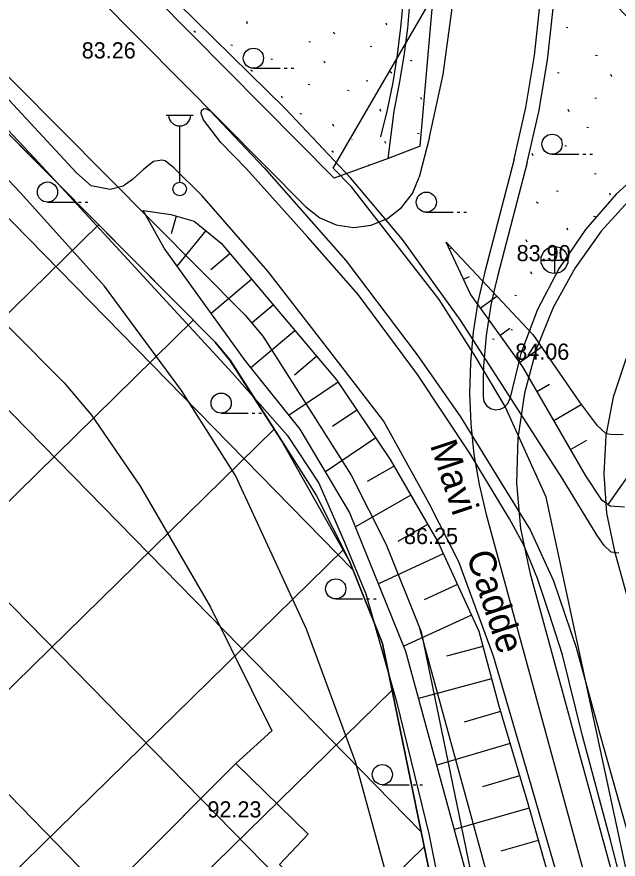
# Model space of a CAD drawing. Extents: x 412225 to 413380, y 4456471 to 4457189.
# Drawn here: x 412488.1 to 412532.8, y 4456751.2 to 4456813.9 of the extents above; entities that cross this region are included whole.
import ezdxf

# ---------------------------------------------------------------- set-up
doc = ezdxf.new("R2010")
doc.units = 0
for name, color, linetype in [('0_HALİHAZIR', 7, 'Continuous'), ('0_KADASTRO', 7, 'Continuous'), ('ADA_KOCEPHE', 7, 'Continuous'), ('ADA_ONCEPHE', 7, 'Continuous'), ('Default', 7, 'Continuous'), ('KALDIRIM', 7, 'Continuous'), ('Level 41', 7, 'Continuous'), ('Level 62', 7, 'Continuous'), ('PL_ORGANIZE_SANAYI', 7, 'Continuous')]:
    doc.layers.add(name, color=color, linetype=linetype)

msp = doc.modelspace()

# ---------------------------------------------------------------- linework, layer by layer
at = {"layer": '0_HALİHAZIR'}
for p, q in [((412505.698, 4456810.048), (412507.698, 4456810.048)), ((412507.998, 4456810.048), (412508.198, 4456810.048)), ((412508.498, 4456810.048), (412508.698, 4456810.048)), ((412499.217, 4456806.569), (412501.217, 4456806.569)), ((412500.217, 4456801.569), (412500.217, 4456805.762)), ((412527.915, 4456803.651), (412529.915, 4456803.651)), ((412530.215, 4456803.651), (412530.415, 4456803.651)), ((412530.715, 4456803.651), (412530.915, 4456803.651)), ((412490.381, 4456800.093), (412492.381, 4456800.093)), ((412492.681, 4456800.093), (412492.881, 4456800.093)), ((412493.181, 4456800.093), (412493.381, 4456800.093)), ((412497.489, 4456799.461), (412497.489, 4456799.461)), ((412518.561, 4456799.339), (412520.561, 4456799.339)), ((412520.861, 4456799.339), (412521.061, 4456799.339)), ((412521.361, 4456799.339), (412521.561, 4456799.339)), ((412499.953, 4456799.054), (412499.587, 4456797.743)), ((412502.155, 4456797.983), (412500.011, 4456795.337)), ((412520.267, 4456796.629), (412520.431, 4456796.705)), ((412528.111, 4456794.781), (412528.111, 4456796.781)), ((412503.963, 4456796.272), (412502.525, 4456795.06)), ((412527.091, 4456795.771), (412529.091, 4456795.771)), ((412505.574, 4456794.361), (412502.554, 4456791.815)), ((412521.317, 4456794.36), (412521.775, 4456794.572)), ((412522.576, 4456792.214), (412523.809, 4456793.102)), ((412507.185, 4456792.449), (412505.603, 4456791.116)), ((412532.084, 4456777.592), (412541.599, 4456791.181)), ((412508.796, 4456790.537), (412505.515, 4456787.772)), ((412524.038, 4456790.185), (412524.785, 4456790.724)), ((412525.5, 4456788.157), (412527.12, 4456789.325)), ((412510.407, 4456788.625), (412508.743, 4456787.223)), ((412511.999, 4456786.699), (412508.348, 4456784.235)), ((412526.783, 4456786.014), (412527.72, 4456786.555)), ((412528.034, 4456783.849), (412530.088, 4456785.036)), ((412503.301, 4456784.395), (412505.301, 4456784.395)), ((412505.601, 4456784.395), (412505.801, 4456784.395)), ((412506.101, 4456784.395), (412506.301, 4456784.395)), ((412513.398, 4456784.627), (412511.589, 4456783.406)), ((412514.797, 4456782.555), (412511.061, 4456780.034)), ((412529.284, 4456781.684), (412530.495, 4456782.384)), ((412516.16, 4456780.461), (412514.166, 4456779.315)), ((412517.406, 4456778.293), (412513.296, 4456775.932)), ((412518.651, 4456776.125), (412516.446, 4456774.858)), ((412519.823, 4456773.92), (412515.005, 4456771.695)), ((412520.871, 4456771.65), (412518.406, 4456770.512)), ((412511.823, 4456770.573), (412513.823, 4456770.573)), ((412514.123, 4456770.573), (412514.323, 4456770.573)), ((412514.623, 4456770.573), (412514.823, 4456770.573)), ((412521.919, 4456769.38), (412516.878, 4456767.052)), ((412522.776, 4456767.041), (412520.052, 4456766.316)), ((412523.419, 4456764.626), (412517.984, 4456763.178)), ((412524.075, 4456762.213), (412521.379, 4456761.413)), ((412524.786, 4456759.817), (412519.339, 4456758.2)), ((412525.497, 4456757.42), (412522.747, 4456756.604)), ((412515.287, 4456756.759), (412517.287, 4456756.759)), ((412517.587, 4456756.759), (412517.787, 4456756.759)), ((412518.087, 4456756.759), (412518.287, 4456756.759)), ((412526.205, 4456755.022), (412520.637, 4456753.433)), ((412526.891, 4456752.618), (412524.092, 4456751.819))]:
    msp.add_line(p, q, dxfattribs=at)
for points in [[(412401.718, 4456891.988), (412412.615, 4456880.806), (412433.47, 4456859.712), (412451.623, 4456841.289), (412475.199, 4456818.459), (412489.407, 4456803.365), (412504.122, 4456787.407), (412508.2, 4456782.766), (412510.554, 4456779.185), (412512.476, 4456774.791), (412514.06, 4456770.952), (412516.347, 4456762.948), (412518.76, 4456753.105), (412521.422, 4456739.666)], [(412404.98, 4456694.18), (412423.333, 4456698.462), (412445.486, 4456703.908), (412473.799, 4456710.815), (412499.682, 4456717.752), (412519.915, 4456723.562), (412520.158, 4456723.713), (412517.3, 4456743.777), (412513.305, 4456758.455), (412509.647, 4456768.326), (412504.376, 4456779.769), (412500.353, 4456786.072), (412494.611, 4456793.85), (412488.36, 4456800.821), (412480.921, 4456808.672), (412468.868, 4456820.827), (412439.58, 4456849.237), (412423.279, 4456864.054), (412404.976, 4456881.973)], [(412532.886, 4456773.972), (412532.31, 4456774.062), (412531.793, 4456774.564), (412531.273, 4456775.296), (412528.663, 4456779.548), (412524.693, 4456785.735), (412521.094, 4456791.304), (412516.782, 4456797.322), (412512.918, 4456801.901), (412508.059, 4456807.056), (412500.088, 4456814.895), (412487.722, 4456827.567), (412472.464, 4456842.514), (412454.647, 4456860.416), (412450.212, 4456864.756)], [(412528.536, 4456749.195), (412526.198, 4456757.33), (412523.551, 4456766.331), (412520.983, 4456773.328), (412518.782, 4456777.685), (412515.372, 4456783.831), (412511.384, 4456789.016), (412506.761, 4456794.948), (412501.879, 4456800.563), (412499.778, 4456802.653), (412499.146, 4456803.153), (412498.882, 4456803.215), (412498.259, 4456803.107), (412497.544, 4456802.538), (412496.7, 4456801.786), (412496.001, 4456801.282), (412495.051, 4456801.022), (412493.634, 4456801.297), (412492.551, 4456802.284), (412483.449, 4456812.078), (412467.576, 4456828.644), (412451.831, 4456844.225), (412437.684, 4456858.482)], [(412398.822, 4456774.408), (412415.24, 4456791.661), (412417.724, 4456789.072), (412426.424, 4456798.47), (412433.963, 4456806.1), (412435.135, 4456805.122), (412440.455, 4456810.55), (412441.248, 4456809.828), (412454.771, 4456823.721), (412491.624, 4456786.662), (412493.665, 4456784.246), (412497.266, 4456778.964), (412502.503, 4456769.956), (412507.058, 4456760.774), (412504.386, 4456758.337), (412474.015, 4456727.896), (412466.982, 4456734.758), (412452.756, 4456720.424), (412454.302, 4456718.456), (412433.608, 4456711.416), (412424.57, 4456720.418), (412409.857, 4456705.946), (412399.424, 4456716.641)], [(412534.073, 4456745.597), (412532.26, 4456752.638), (412530.191, 4456760.399), (412528.689, 4456766.426), (412527.707, 4456769.485), (412526.831, 4456772.085), (412525.825, 4456774.569), (412524.76, 4456776.542), (412521.829, 4456781.381), (412517.913, 4456787.274), (412513.487, 4456793.225), (412509.743, 4456797.476), (412505.181, 4456802.57), (412503.278, 4456804.531), (412501.988, 4456806.205), (412501.817, 4456806.696), (412501.846, 4456806.91), (412501.976, 4456807.043), (412502.124, 4456807.046), (412502.471, 4456806.886), (412506.511, 4456802.656), (412512.579, 4456795.742), (412517.892, 4456788.736), (412521.115, 4456784.132), (412524.146, 4456779.163), (412526.284, 4456775.71), (412528.033, 4456771.922), (412529.7, 4456766.966), (412531.506, 4456760.353), (412533.847, 4456752.054)], [(412475.121, 4456705.083), (412490.775, 4456709.159), (412513.671, 4456714.77), (412517.534, 4456715.862), (412518.766, 4456715.913), (412521.888, 4456714.841), (412523.641, 4456714.127), (412524.431, 4456714.04), (412525.187, 4456714.051), (412525.773, 4456714.455), (412526.781, 4456716.359), (412527.429, 4456718.111), (412527.386, 4456718.801), (412527.045, 4456719.618), (412526.551, 4456720.794), (412525.86, 4456724.186), (412523.964, 4456740.283), (412521.987, 4456748.472), (412517.036, 4456766.66), (412512.857, 4456777.02), (412509.167, 4456783.212), (412505.082, 4456788.313), (412499.059, 4456796.657), (412497.489, 4456799.461)], [(412497.489, 4456799.461), (412499.565, 4456799.162), (412501.298, 4456798.678), (412503.31, 4456797.048), (412511.875, 4456786.884), (412515.873, 4456780.96), (412519.432, 4456774.766), (412522.471, 4456768.186), (412523.949, 4456762.636), (412526.11, 4456755.354), (412528.848, 4456745.762)], [(412533.311, 4456777.415), (412532.242, 4456777.481), (412531.644, 4456777.9), (412530.417, 4456779.723), (412525.729, 4456787.84), (412521.836, 4456793.24), (412520.037, 4456797.125)], [(412520.037, 4456797.125), (412526.482, 4456790.25), (412529.959, 4456785.206), (412531.232, 4456783.532), (412531.916, 4456782.884), (412532.295, 4456782.824), (412533.199, 4456782.805)]]:
    msp.add_lwpolyline(points, dxfattribs=at)
msp.add_lwpolyline([(412473.039, 4456726.918), (412504.386, 4456758.337), (412509.781, 4456753.082), (412507.628, 4456750.816), (412510.062, 4456748.339), (412507.41, 4456745.674), (412510.09, 4456743.12), (412500.895, 4456733.883), (412498.976, 4456735.747), (412495.42, 4456732.351), (412497.194, 4456730.436), (412488.392, 4456721.124), (412485.649, 4456723.514), (412483.287, 4456721.065), (412480.623, 4456723.636), (412478.355, 4456721.434)], close=True, dxfattribs=at)
for centre, radius in [((412505.698, 4456810.798), 0.75), ((412527.915, 4456804.401), 0.75), ((412490.381, 4456800.843), 0.75), ((412500.217, 4456801.069), 0.5), ((412518.561, 4456800.089), 0.75), ((412528.096, 4456795.789), 1), ((412503.301, 4456785.145), 0.75), ((412511.823, 4456771.323), 0.75), ((412515.287, 4456757.509), 0.75)]:
    msp.add_circle(centre, radius, dxfattribs=at)
msp.add_arc((412500.217, 4456806.599), 0.837, 183.298, 356.90719, dxfattribs=at)
at = {"layer": '0_KADASTRO'}
for p, q in [((412503.956, 4456788.339), (412502.86, 4456789.67)), ((412507.79, 4456782.361), (412503.956, 4456788.339)), ((412512.839, 4456773.391), (412507.79, 4456782.361)), ((412515.298, 4456767.27), (412512.839, 4456773.391)), ((412524.48, 4456722.711), (412515.298, 4456767.27))]:
    msp.add_line(p, q, dxfattribs=at)
msp.add_lwpolyline([(412502.86, 4456789.67), (412478.924, 4456813.779), (412405.36, 4456888.28)], dxfattribs=at)
msp.add_lwpolyline([(412511.64, 4456802.61), (412523.869, 4456823.705), (412617.056, 4456728.859), (412543.593, 4456703.12), (412527.466, 4456778.138), (412524.42, 4456784.89), (412522.24, 4456788.56), (412519.52, 4456792.85), (412512.99, 4456801.24)], close=True, dxfattribs=at)
at = {"layer": 'ADA_KOCEPHE'}
for p, q in [((412511.712, 4456801.864), (412285.694, 4457030.12)), ((412478.92, 4456813.78), (412502.86, 4456789.67)), ((412478.92, 4456813.78), (412502.86, 4456789.67)), ((412502.86, 4456789.67), (412503.96, 4456788.34)), ((412502.86, 4456789.67), (412503.96, 4456788.34)), ((412503.96, 4456788.34), (412507.79, 4456782.36)), ((412503.96, 4456788.34), (412507.79, 4456782.36)), ((412507.79, 4456782.36), (412510.36, 4456778.29)), ((412507.79, 4456782.36), (412510.36, 4456778.29)), ((412510.36, 4456778.29), (412512.84, 4456773.39)), ((412510.36, 4456778.29), (412512.84, 4456773.39)), ((412512.84, 4456773.39), (412515.3, 4456767.27)), ((412512.84, 4456773.39), (412515.3, 4456767.27)), ((412515.3, 4456767.27), (412524.48, 4456722.71)), ((412515.3, 4456767.27), (412524.48, 4456722.71))]:
    msp.add_line(p, q, dxfattribs=at)
at = {"layer": 'ADA_ONCEPHE'}
for p, q in [((412518.104, 4456804.245), (412519.643, 4456821.8)), ((412516.677, 4456813.093), (412516.86, 4456815.155)), ((412517.174, 4456813.04), (412517.359, 4456815.12)), ((412516.418, 4456811.039), (412516.677, 4456813.093)), ((412516.913, 4456810.968), (412517.174, 4456813.04)), ((412516.084, 4456808.997), (412516.418, 4456811.039)), ((412516.575, 4456808.907), (412516.913, 4456810.968)), ((412515.674, 4456806.968), (412516.084, 4456808.997)), ((412516.162, 4456806.859), (412516.575, 4456808.907)), ((412515.189, 4456804.955), (412515.674, 4456806.968)), ((412515.729, 4456803.327), (412516.162, 4456806.859)), ((412515.189, 4456804.955), (412515.189, 4456804.955)), ((412518.104, 4456804.245), (412515.729, 4456803.327)), ((412515.729, 4456803.327), (412511.712, 4456801.864))]:
    msp.add_line(p, q, dxfattribs=at)
at = {"layer": 'Default'}
for p, q in [((412513.1, 4456772.743), (412245.17, 4457046.214)), ((412518.186, 4456753.263), (412245.006, 4457032.093)), ((412521.913, 4456735.169), (412244.841, 4457017.971)), ((412523.399, 4456719.363), (412244.677, 4457003.85)), ((412375.624, 4456682.255), (412494.182, 4456798.41)), ((412394.62, 4456686.867), (412501.228, 4456791.314)), ((412413.671, 4456691.531), (412507.245, 4456783.21)), ((412432.721, 4456696.196), (412512.4, 4456774.26)), ((412451.771, 4456700.861), (412516.014, 4456763.802)), ((412470.822, 4456705.526), (412518.414, 4456752.154))]:
    msp.add_line(p, q, dxfattribs=at)
at = {"layer": 'KALDIRIM'}
for p, q in [((412509.598, 4456799.736), (412281.429, 4457030.164)), ((412518.798, 4456804.923), (412518.025, 4456801.958)), ((412526.055, 4456803.033), (412523.872, 4456794.649)), ((412523.012, 4456776.859), (412539.12, 4456717.88)), ((412526.266, 4456772.534), (412533.526, 4456745.952)), ((412518.037, 4456768.506), (412529.137, 4456727.864))]:
    msp.add_line(p, q, dxfattribs=at)
for points in [[(412245.253, 4457053.382), (412266.323, 4457032.279), (412337.147, 4456961.286), (412407.492, 4456890.39), (412481.052, 4456815.891), (412505.085, 4456791.687), (412506.388, 4456790.112), (412510.321, 4456783.97), (412512.973, 4456779.772), (412515.575, 4456774.629), (412518.184, 4456768.139), (412527.355, 4456723.622)], [(412268.299, 4457030.299), (412337.147, 4456961.286), (412407.492, 4456890.39), (412481.052, 4456815.891), (412505.085, 4456791.687), (412506.388, 4456790.112), (412510.321, 4456783.97), (412512.973, 4456779.772), (412515.575, 4456774.629), (412518.037, 4456768.506)], [(412526.055, 4456803.033), (412526.925, 4456806.817), (412527.576, 4456810.644), (412528.006, 4456814.502), (412528.213, 4456818.379), (412528.198, 4456822.261), (412527.959, 4456826.136), (412527.497, 4456829.991), (412526.815, 4456833.812)], [(412551.215, 4456809.433), (412547.768, 4456808.928), (412544.404, 4456808.02), (412541.171, 4456806.722), (412538.114, 4456805.052), (412535.275, 4456803.034), (412532.693, 4456800.694), (412530.406, 4456798.067), (412528.444, 4456795.188), (412526.835, 4456792.098), (412525.601, 4456788.84), (412524.761, 4456785.459)], [(412509.598, 4456799.736), (412510.634, 4456798.919), (412511.847, 4456798.401), (412513.153, 4456798.218), (412514.461, 4456798.383), (412515.681, 4456798.885), (412516.727, 4456799.688), (412517.527, 4456800.736), (412518.025, 4456801.958)], [(412523.872, 4456794.649), (412523.604, 4456793.542), (412523.372, 4456792.427), (412523.178, 4456791.305), (412523.022, 4456790.176), (412522.904, 4456789.043), (412522.824, 4456787.907), (412522.782, 4456786.769), (412522.778, 4456785.63)], [(412522.778, 4456785.63), (412522.85, 4456785.271), (412523.046, 4456784.962), (412523.339, 4456784.744), (412523.692, 4456784.647), (412524.056, 4456784.683), (412524.383, 4456784.847), (412524.629, 4456785.118), (412524.761, 4456785.459)]]:
    msp.add_lwpolyline(points, dxfattribs=at)
at = {"layer": 'Level 41'}
for p, q in [((412502.747, 4456813.654), (412502.756, 4456813.652)), ((412502.747, 4456813.654), (412502.756, 4456813.652)), ((412505.264, 4456813.358), (412505.2, 4456813.521)), ((412505.264, 4456813.358), (412505.2, 4456813.521)), ((412513.114, 4456813.548), (412513.123, 4456813.546)), ((412513.114, 4456813.548), (412513.123, 4456813.546)), ((412515.631, 4456813.252), (412515.568, 4456813.415)), ((412515.631, 4456813.252), (412515.568, 4456813.415)), ((412528.964, 4456813.116), (412529.09, 4456813.09)), ((412528.964, 4456813.116), (412529.09, 4456813.09)), ((412501.263, 4456812.83), (412501.39, 4456812.73)), ((412501.263, 4456812.83), (412501.39, 4456812.73)), ((412511.631, 4456812.724), (412511.757, 4456812.624)), ((412511.631, 4456812.724), (412511.757, 4456812.624)), ((412504.008, 4456811.803), (412504.134, 4456811.778)), ((412504.008, 4456811.803), (412504.134, 4456811.778)), ((412509.83, 4456812.038), (412509.956, 4456812.012)), ((412509.83, 4456812.038), (412509.956, 4456812.012)), ((412514.375, 4456811.697), (412514.501, 4456811.672)), ((412514.375, 4456811.697), (412514.501, 4456811.672)), ((412506.996, 4456810.748), (412507.121, 4456810.722)), ((412506.996, 4456810.748), (412507.121, 4456810.722)), ((412511.027, 4456810.427), (412510.964, 4456810.59)), ((412511.027, 4456810.427), (412510.964, 4456810.59)), ((412517.364, 4456810.642), (412517.489, 4456810.616)), ((412517.364, 4456810.642), (412517.489, 4456810.616)), ((412531.157, 4456811.025), (412531.283, 4456810.999)), ((412531.157, 4456811.025), (412531.283, 4456810.999)), ((412505.513, 4456809.925), (412505.639, 4456809.825)), ((412505.513, 4456809.925), (412505.639, 4456809.825)), ((412515.88, 4456809.819), (412516.007, 4456809.719)), ((412515.88, 4456809.819), (412516.007, 4456809.719)), ((412528.324, 4456809.735), (412528.449, 4456809.71)), ((412528.324, 4456809.735), (412528.449, 4456809.71)), ((412532.354, 4456809.415), (412532.291, 4456809.578)), ((412532.354, 4456809.415), (412532.291, 4456809.578)), ((412509.771, 4456808.872), (412509.897, 4456808.847)), ((412509.771, 4456808.872), (412509.897, 4456808.847)), ((412514.079, 4456809.132), (412514.205, 4456809.107)), ((412514.079, 4456809.132), (412514.205, 4456809.107)), ((412507.857, 4456807.823), (412507.792, 4456807.986)), ((412507.857, 4456807.823), (412507.792, 4456807.986)), ((412512.696, 4456808.432), (412512.822, 4456808.407)), ((412512.696, 4456808.432), (412512.822, 4456808.407)), ((412518.224, 4456807.717), (412518.16, 4456807.879)), ((412518.224, 4456807.717), (412518.16, 4456807.879)), ((412531.098, 4456807.859), (412531.224, 4456807.835)), ((412531.098, 4456807.859), (412531.224, 4456807.835)), ((412515.184, 4456806.833), (412515.12, 4456806.997)), ((412515.184, 4456806.833), (412515.12, 4456806.997)), ((412529.184, 4456806.81), (412529.12, 4456806.973)), ((412529.184, 4456806.81), (412529.12, 4456806.973)), ((412509.164, 4456806.674), (412509.29, 4456806.649)), ((412509.164, 4456806.674), (412509.29, 4456806.649)), ((412511.676, 4456805.72), (412511.614, 4456805.881)), ((412511.676, 4456805.72), (412511.614, 4456805.881)), ((412530.491, 4456805.661), (412530.617, 4456805.637)), ((412530.491, 4456805.661), (412530.617, 4456805.637)), ((412517.914, 4456805.217), (412518.04, 4456805.191)), ((412517.914, 4456805.217), (412518.04, 4456805.191)), ((412513.024, 4456804.742), (412513.033, 4456804.74)), ((412513.024, 4456804.742), (412513.033, 4456804.74)), ((412515.541, 4456804.447), (412515.478, 4456804.61)), ((412515.541, 4456804.447), (412515.478, 4456804.61)), ((412528.873, 4456804.31), (412529, 4456804.285)), ((412528.873, 4456804.31), (412529, 4456804.285)), ((412511.541, 4456803.918), (412511.667, 4456803.819)), ((412511.541, 4456803.918), (412511.667, 4456803.819)), ((412526.501, 4456803.54), (412526.438, 4456803.703)), ((412526.501, 4456803.54), (412526.438, 4456803.703)), ((412514.285, 4456802.891), (412514.411, 4456802.867)), ((412514.285, 4456802.891), (412514.411, 4456802.867)), ((412531.067, 4456802.219), (412531.193, 4456802.194)), ((412531.067, 4456802.219), (412531.193, 4456802.194)), ((412528.234, 4456800.93), (412528.359, 4456800.904)), ((412528.234, 4456800.93), (412528.359, 4456800.904)), ((412532.264, 4456800.609), (412532.201, 4456800.772)), ((412532.264, 4456800.609), (412532.201, 4456800.772)), ((412526.75, 4456800.107), (412526.876, 4456800.006)), ((412526.75, 4456800.107), (412526.876, 4456800.006)), ((412531.008, 4456799.054), (412531.134, 4456799.029)), ((412531.008, 4456799.054), (412531.134, 4456799.029)), ((412529.094, 4456798.004), (412529.03, 4456798.167)), ((412529.094, 4456798.004), (412529.03, 4456798.167)), ((412526.053, 4456797.121), (412525.99, 4456797.285)), ((412526.053, 4456797.121), (412525.99, 4456797.285)), ((412526.411, 4456794.735), (412526.347, 4456794.897)), ((412526.411, 4456794.735), (412526.347, 4456794.897)), ((412525.155, 4456793.179), (412525.281, 4456793.154)), ((412525.155, 4456793.179), (412525.281, 4456793.154)), ((412524.858, 4456790.614), (412524.984, 4456790.59)), ((412524.858, 4456790.614), (412524.984, 4456790.59)), ((412523.475, 4456789.915), (412523.601, 4456789.889)), ((412523.475, 4456789.915), (412523.601, 4456789.889)), ((412523.804, 4456786.224), (412523.812, 4456786.222)), ((412523.804, 4456786.224), (412523.812, 4456786.222))]:
    msp.add_line(p, q, dxfattribs=at)
at = {"layer": 'Level 62'}
for p, q in [((412525.088, 4456803.285), (412522.904, 4456794.901)), ((412532.569, 4456774.127), (412538.45, 4456752.595))]:
    msp.add_line(p, q, dxfattribs=at)
for points in [[(412518.798, 4456804.923), (412519.816, 4456809.588), (412520.46, 4456814.319), (412520.726, 4456819.086), (412520.613, 4456823.859), (412520.12, 4456828.608), (412519.251, 4456833.303), (412518.011, 4456837.914), (412516.409, 4456842.412), (412514.454, 4456846.768), (412512.159, 4456850.955), (412509.538, 4456854.946), (412506.609, 4456858.716), (412503.388, 4456862.241)], [(412525.088, 4456803.285), (412525.967, 4456807.123), (412526.617, 4456811.007), (412527.036, 4456814.922), (412527.223, 4456818.855), (412527.177, 4456822.792), (412526.898, 4456826.72), (412526.387, 4456830.624), (412525.646, 4456834.491)], [(412551.912, 4456808.483), (412548.572, 4456808.067), (412545.304, 4456807.26), (412542.155, 4456806.073), (412539.167, 4456804.524), (412536.382, 4456802.632), (412533.84, 4456800.426), (412531.576, 4456797.936), (412529.621, 4456795.195), (412528.003, 4456792.244), (412526.744, 4456789.122), (412525.862, 4456785.874), (412525.369, 4456782.544), (412525.272, 4456779.18), (412525.573, 4456775.827), (412526.266, 4456772.534)], [(412569.399, 4456795.515), (412567.232, 4456797.435), (412564.832, 4456799.053), (412562.239, 4456800.343), (412559.5, 4456801.28), (412556.662, 4456801.85), (412553.773, 4456802.043), (412550.884, 4456801.854), (412548.045, 4456801.288), (412545.305, 4456800.354), (412542.711, 4456799.068), (412540.309, 4456797.452), (412538.139, 4456795.535), (412536.24, 4456793.35), (412534.644, 4456790.934), (412533.38, 4456788.33), (412532.468, 4456785.582), (412531.925, 4456782.739), (412531.76, 4456779.848), (412531.976, 4456776.961), (412532.569, 4456774.127)], [(412522.904, 4456794.901), (412522.402, 4456792.677), (412522.045, 4456790.424), (412521.836, 4456788.153), (412521.775, 4456785.873), (412521.863, 4456783.594), (412522.099, 4456781.326), (412522.483, 4456779.078), (412523.012, 4456776.859)]]:
    msp.add_lwpolyline(points, dxfattribs=at)
at = {"layer": 'PL_ORGANIZE_SANAYI'}
for p, q in [((412478.92, 4456813.78), (412502.86, 4456789.67)), ((412502.86, 4456789.67), (412503.96, 4456788.34)), ((412503.96, 4456788.34), (412507.79, 4456782.36)), ((412507.79, 4456782.36), (412510.36, 4456778.29)), ((412510.36, 4456778.29), (412512.84, 4456773.39)), ((412512.84, 4456773.39), (412515.3, 4456767.27)), ((412515.3, 4456767.27), (412524.48, 4456722.71))]:
    msp.add_line(p, q, dxfattribs=at)

# ---------------------------------------------------------------- texts
at = {"layer": '0_HALİHAZIR'}
for s, p in [('83.26', (412492.932, 4456810.784)), ('83.90', (412525.279, 4456795.701)), ('84.06', (412525.179, 4456788.37)), ('86.25', (412516.906, 4456774.658)), ('92.23', (412502.281, 4456754.324))]:
    msp.add_text(s, height=1.2, dxfattribs=at).set_placement(p)
msp.add_text('Mavi    Cadde', height=2, rotation=288.26293, dxfattribs=at).set_placement((412518.819, 4456782.023))

doc.saveas('drawing.dxf')
